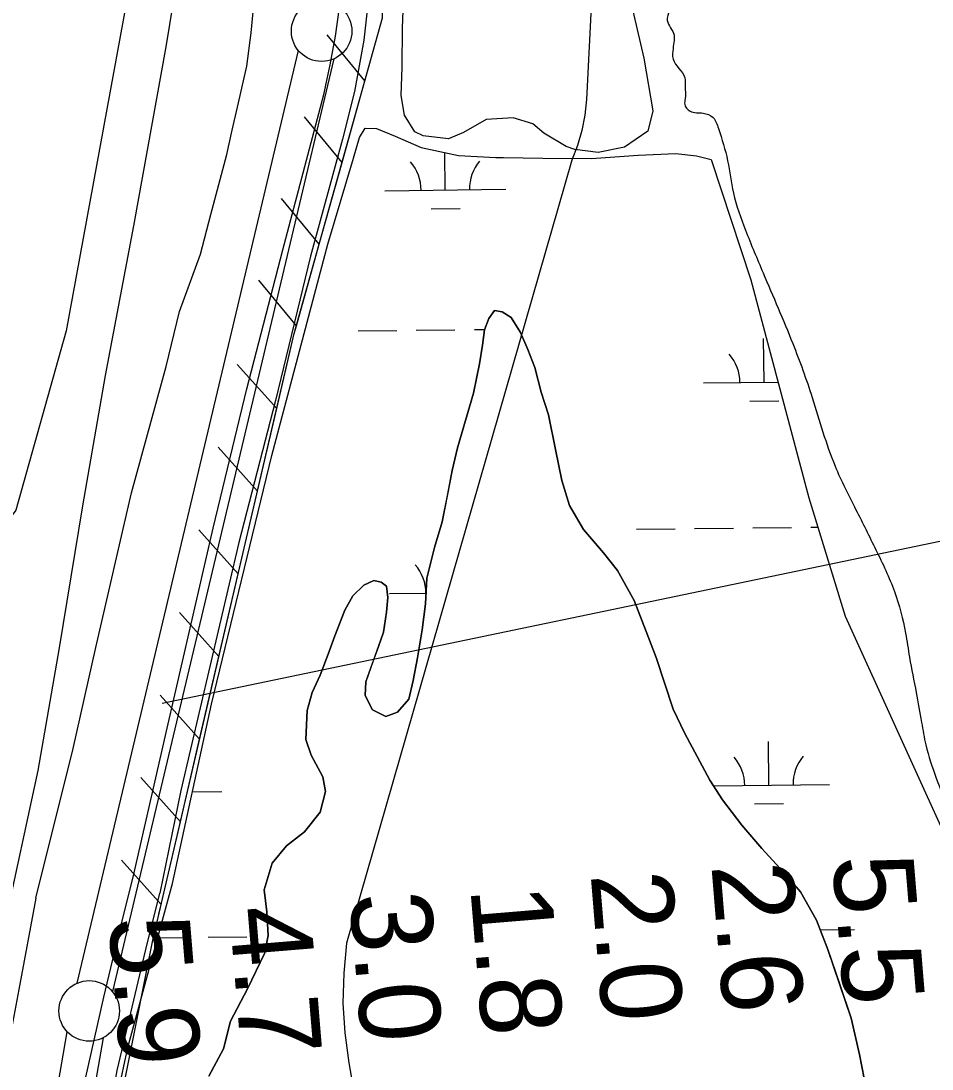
# Model space of a CAD drawing. Extents: x 3694830 to 3732949, y 415201 to 440970.
# Drawn here: x 3715805 to 3716558, y 422528 to 423394 of the extents above; entities that cross this region are included whole.
import ezdxf

# ---------------------------------------------------------------- set-up
doc = ezdxf.new("R2010")
doc.units = 0
for name, color, linetype in [('V-FLOD-BASE', 7, 'Continuous'), ('V-LEVE-TOET', 7, 'Continuous'), ('V-RAIL-TRAK', 7, 'Continuous'), ('V-RIVR-EDGE', 7, 'Continuous'), ('V-RIVR-RANG', 7, 'Continuous'), ('V-RRAP-FSHR', 7, 'Continuous'), ('V-SITE-VEGE', 7, 'Continuous'), ('V-SURV-LINE', 7, 'Continuous'), ('V-TOPO-MINR', 7, 'Continuous'), ('V-TOPO-SHOR', 7, 'Continuous'), ('V-WETL-SWMP', 7, 'Continuous')]:
    doc.layers.add(name, color=color, linetype=linetype)

msp = doc.modelspace()

# ---------------------------------------------------------------- linework, layer by layer
at = {"layer": 'V-FLOD-BASE'}
for points in [[(3716053.01, 423322.64), (3716055.87, 423334.29), (3716058.52, 423345.99), (3716060.97, 423357.73), (3716063.21, 423369.52), (3716065.24, 423381.34), (3716067.06, 423393.2), (3716068.68, 423405.09)], [(3715898.13, 422686.87), (3715926.21, 422809.82), (3715964.19, 422974.98), (3715992.2, 423090), (3716021.8, 423205), (3716053.01, 423322.64)], [(3715861.32, 422013.21), (3715856.48, 422048.35), (3715852.1, 422088.59), (3715850.36, 422117.12), (3715849.12, 422214.47), (3715844.99, 422359.72), (3715844.17, 422401), (3715846.46, 422436.71), (3715848.37, 422453.54), (3715851.79, 422474.47), (3715858.59, 422519.38), (3715873.88, 422587.8), (3715886.74, 422641.92), (3715898.13, 422686.87)]]:
    msp.add_lwpolyline(points, dxfattribs=at)
at = {"layer": 'V-LEVE-TOET'}
for points in [[(3715817.73, 422669.64), (3715848.46, 422793.09), (3715867.2, 422876.47), (3715896.91, 423004.17), (3715925.35, 423108.6), (3715936.34, 423153.98), (3715953.69, 423201.41), (3715962.45, 423234.11), (3715975.59, 423283.7), (3715980, 423303.75), (3715984.4, 423322.75), (3715992.11, 423356.52), (3715995.53, 423383.98), (3716001.38, 423445.27)], [(3716092.74, 423415.43), (3716088.7, 423377.92), (3716080.91, 423335.69), (3716071.03, 423296.12), (3716044.78, 423199.59), (3716015.67, 423080.35), (3715985.53, 422963.24), (3715937.67, 422758.51), (3715920.18, 422673.62)], [(3715817.73, 422669.64), (3715803.59, 422594.17), (3715792.1, 422532.51), (3715786.01, 422485.59), (3715780.9, 422431.33), (3715777.63, 422376.16), (3715777.98, 422329.3), (3715781.11, 422279.69), (3715790.05, 422189.69), (3715797.1, 422106.11), (3715807.99, 422000.49)], [(3715877.82, 422064.43), (3715874.08, 422073.13), (3715867.06, 422091.46), (3715866.07, 422100.19), (3715866.75, 422132.36), (3715866.05, 422164.52), (3715865.85, 422253.2), (3715864.71, 422345.56), (3715865.33, 422386.46), (3715865.55, 422418.63), (3715866.41, 422427.09), (3715867.52, 422435.51), (3715868.87, 422443.9), (3715870.46, 422452.25), (3715872.29, 422460.55), (3715874.37, 422468.79), (3715884.96, 422527.23), (3715908.58, 422627.12), (3715920.18, 422673.62)]]:
    msp.add_lwpolyline(points, dxfattribs=at)
at = {"layer": 'V-RAIL-TRAK'}
msp.add_lwpolyline([(3715982.46, 424206.42), (3715993.76, 424052.97), (3715994.57, 424025.46), (3715995.29, 423987.39), (3715994.86, 423940.86), (3715989.91, 423860.53), (3715973.5, 423684.07), (3715949.84, 423523.54), (3715925.2, 423372.53), (3715898.48, 423224.71), (3715875.15, 423101.19), (3715856.2, 422993.49), (3715837.16, 422876.28), (3715819.32, 422774.92), (3715791.71, 422646.15)], dxfattribs=at)
at = {"layer": 'V-RIVR-EDGE'}
for points in [[(3716285.15, 433216.71), (3716310.38, 433178.21), (3716330.2, 433149.68), (3716351.38, 433122.49), (3716380.66, 433076.75), (3716399.14, 433050.48), (3716447.79, 432976.21), (3716475.25, 432930.47), (3716501.83, 432891.07), (3716527.51, 432851.22), (3716586.04, 432749.34), (3716608.1, 432711.75), (3716608.09, 432707.68), (3716608.07, 432700.45), (3716613.02, 432690.94), (3716627.43, 432664.23), (3716633.27, 432651.55), (3716643.19, 432639.32), (3716675.17, 432589.5), (3716706.24, 432538.33), (3716726.94, 432498.04), (3716741.33, 432463.64), (3716748.51, 432442.82), (3716788.59, 432378.52), (3716817.43, 432339.56), (3716842.2, 432297.45), (3716889.46, 432209.61), (3716920.5, 432144.42), (3716938.04, 432109.56), (3716956.5, 432075.15), (3716988.92, 432022.62), (3717009.18, 431986.85), (3717026.3, 431960.13), (3717062.32, 431897.65), (3717093.37, 431840.15), (3717112.26, 431799.86), (3717149.12, 431711.14), (3717176.54, 431644.61), (3717201.25, 431580.79), (3717210.68, 431556.35), (3717248.47, 431478.94), (3717267.81, 431435.48), (3717289.41, 431392.93), (3717306.48, 431346.77), (3717328.07, 431301.04), (3717339.31, 431276.6), (3717352.34, 431244.01), (3717362.7, 431226.35), (3717376.21, 431205.52), (3717389.26, 431178.36), (3717401.37, 431141.7), (3717407.18, 431113.2), (3717409.87, 431101.89), (3717419.75, 431075.64), (3717452.49, 430968.85), (3717469.09, 430916.81), (3717483.44, 430865.23), (3717505.45, 430810.01), (3717526.57, 430753.44), (3717540.49, 430715.43), (3717579.07, 430593.25), (3717599.25, 430526.28), (3717616.31, 430474.69), (3717628.88, 430437.13), (3717638.74, 430405), (3717647.69, 430364.28), (3717653.48, 430331.72), (3717658.42, 430314.52), (3717667.85, 430290.08), (3717679.53, 430260.66), (3717690.34, 430242.1), (3717695.71, 430221.28), (3717698.37, 430200.03), (3717697.85, 430171.99), (3717701.42, 430152.99), (3717705.91, 430140.77), (3717716.26, 430119.95), (3717727.97, 430100.48), (3717735.6, 430076.49), (3717737.82, 430059.31), (3717749.05, 430029.89), (3717760.76, 430011.77), (3717771.56, 429990.04), (3717776.48, 429968.33), (3717783.19, 429941.63), (3717791.73, 429917.65), (3717803.43, 429898.63), (3717812.42, 429876.45), (3717819.16, 429857.44), (3717834.88, 429816.71), (3717846.52, 429770.11), (3717854.12, 429734.82), (3717863.55, 429706.31), (3717878.83, 429667.39), (3717891.37, 429622.59), (3717903.49, 429586.39), (3717917.82, 429530.29), (3717931.71, 429476.45), (3717959.46, 429363.79), (3717976.51, 429307.23), (3717987.25, 429262.44), (3718014.11, 429153.85), (3718027.51, 429090.07), (3718040.47, 429028.09), (3718052.52, 428962.5), (3718057.84, 428919.98), (3718056.9, 428903.25), (3718056.86, 428887.88), (3718057.71, 428868.43), (3718061.29, 428850.79), (3718065.77, 428833.6), (3718082.36, 428779.3), (3718091.33, 428748.08), (3718100.28, 428710.98), (3718111.45, 428657.14), (3718116.36, 428631.81), (3718128.31, 428525.97), (3718136.77, 428473.05), (3718141.66, 428440.03), (3718152.32, 428360.88), (3718163.9, 428291.22), (3718171.05, 428256.38), (3718178.23, 428236.47), (3718193.92, 428178.55), (3718199.74, 428157.29), (3718197.91, 428150.06), (3718196.52, 428133.33), (3718197.39, 428121.12), (3718204.12, 428098.04), (3718215.36, 428075.41), (3718227.96, 428049.6), (3718240.08, 428011.59), (3718242.71, 427978.58), (3718251.11, 427901.24), (3718254.15, 427852.85), (3718257.69, 427822.1), (3718271.5, 427736.15), (3718281.74, 427671.92), (3718287.91, 427606.34), (3718295.91, 427551.61), (3718303.87, 427477.44), (3718310.12, 427447.13), (3718323.14, 427407.76), (3718345.15, 427350.28), (3718351.41, 427321.78), (3718363.48, 427267.49), (3718378.28, 427217.26), (3718397.99, 427141.25), (3718402.87, 427105.52), (3718405.92, 427056.68), (3718404.86, 426993.38), (3718419.58, 426915.12), (3718427.13, 426857.67), (3718428.77, 426789.85), (3718439.53, 426753.19), (3718453.89, 426709.75), (3718458.33, 426677.18), (3718461.82, 426625.18), (3718465.34, 426583.57), (3718482.71, 426479.53), (3718492.52, 426423.89), (3718501, 426378.2), (3718502.74, 426350.16), (3718512.91, 426256.09), (3718518.23, 426213.12), (3718524.03, 426182.81), (3718533.44, 426148.88), (3718540.93, 426069.28), (3718548.93, 426010.93), (3718557.81, 425944.44), (3718573.42, 425858.94), (3718584.55, 425787.48), (3718587.61, 425745.42), (3718587.56, 425725.97), (3718607.51, 425567.22), (3718614.55, 425488.07), (3718638.22, 425368.64), (3718641.26, 425318.45), (3718641.09, 425249.72), (3718640.1, 425214), (3718649.84, 425130.78), (3718658.73, 425069.26), (3718661.82, 425037.15), (3718660.41, 425016.36), (3718674.96, 424864.4), (3718675.73, 424812.85), (3718692.62, 424694.79), (3718696.05, 424618.82), (3718696.4, 424575.87), (3718706.12, 424484.51), (3718711.87, 424431.59), (3718715.41, 424403.09), (3718735.93, 424289.1), (3718746.6, 424215.37), (3718759.9, 424108.63), (3718772.36, 424027.21), (3718777.72, 423998.26), (3718795.91, 423858.04), (3718805.72, 423804.21), (3718812.44, 423776.61), (3718829, 423707.39), (3718835.67, 423662.61), (3718835.09, 423611.97), (3718835, 423576.7), (3718839.35, 423505.25), (3718842.4, 423460.03), (3718850.42, 423412.53), (3718863.4, 423357.79), (3718870.56, 423326.57), (3718873.56, 423260.55), (3718878.86, 423208.99), (3718893.63, 423148.36), (3718899, 423126.2), (3718912.45, 423080.04), (3718927.23, 423022.58), (3718930.77, 422992.73), (3718937.45, 422950.21), (3718945.92, 422900.45), (3718952.63, 422870.59), (3718968.72, 422795.95), (3718969.56, 422769.72), (3718968.13, 422738.52), (3718972.12, 422707.77), (3718981.05, 422661.17), (3718990.85, 422602.82), (3719006.89, 422506.47), (3719010.81, 422446.32), (3719014.37, 422425.06), (3719022.44, 422393.39), (3719033.2, 422359), (3719050.26, 422307.87), (3719062.77, 422249.05), (3719077.1, 422190.24), (3719087.85, 422149.06)], [(3716330.82, 423439.35), (3716341.85, 423407.99), (3716341.03, 423402.33), (3716339.39, 423394.25), (3716345.02, 423382.1), (3716345.01, 423377.65), (3716344.18, 423371.18), (3716344.16, 423362.29), (3716353.83, 423346.9), (3716354.22, 423340.02), (3716354.19, 423329.51), (3716353.78, 423325.06), (3716358.21, 423319.39), (3716369.12, 423317.75), (3716377.2, 423314.09), (3716381.63, 423305.18), (3716389.24, 423278.47), (3716394.03, 423251.77), (3716404.06, 423221.02), (3716418.53, 423185.8), (3716443.06, 423127.51), (3716459.12, 423082.99), (3716477.99, 423026.33), (3716495.29, 422990.3), (3716511.78, 422957.1), (3716527.06, 422922.69), (3716536.28, 422888.3), (3716539.46, 422868.47), (3716545.05, 422839.35), (3716549.44, 422814.67), (3716553.03, 422796.06), (3716571.9, 422741.42), (3716593.58, 422675.05), (3716607.64, 422637.82), (3716616.87, 422610.7), (3716635.34, 422558.09), (3716647.38, 422520.45), (3716673.89, 422447)]]:
    msp.add_spline(points, degree=3, dxfattribs=at)
at = {"layer": 'V-RIVR-RANG'}
msp.add_line((3715922.14, 422830.69), (3716901.18, 423034.35), dxfattribs=at)
at = {"layer": 'V-RRAP-FSHR'}
for p, q in [((3716089.55, 423344.5), (3716058.52, 423382.27)), ((3716070.71, 423277), (3716039.68, 423314.78)), ((3716051.87, 423209.51), (3716020.84, 423247.28)), ((3716033.03, 423142.01), (3716002, 423179.78)), ((3716016.83, 423073.84), (3715984.21, 423110.25)), ((3716000.89, 423005.6), (3715968.27, 423042.01)), ((3715984.95, 422937.36), (3715952.33, 422973.77)), ((3715969.01, 422869.12), (3715936.39, 422905.53)), ((3715953.07, 422800.88), (3715920.46, 422837.29)), ((3715937.14, 422732.64), (3715904.52, 422769.05)), ((3715921.2, 422664.4), (3715888.58, 422700.81))]:
    msp.add_line(p, q, dxfattribs=at)
for points in [[(3716641.15, 420826.04), (3716497.1, 420943.72), (3716411.63, 421060.5), (3716364.3, 421170.5), (3716321.83, 421303.9), (3716285.1, 421373.79), (3716186.8, 421473.87), (3716066.75, 421590.93), (3715980.47, 421690.03), (3715930.26, 421828.72), (3715913.48, 421896.78), (3715879.02, 422073.91), (3715879.91, 422256.34), (3715873.14, 422428), (3715914.01, 422633.62), (3716031.29, 423135.79), (3716104.08, 423396.54), (3716111.44, 423811.54), (3716102.74, 424148.37), (3716065.57, 424473.12), (3715995.1, 425269.77), (3715894.16, 426351.13), (3715758.55, 427758.05)], [(3716089.55, 423344.5), (3716093.62, 423359.05)], [(3716070.71, 423277), (3716089.55, 423344.5)], [(3716051.87, 423209.51), (3716070.71, 423277)], [(3716033.03, 423142.01), (3716051.87, 423209.51)], [(3716016.83, 423073.84), (3716031.29, 423135.79), (3716033.03, 423142.01)], [(3716000.89, 423005.6), (3716016.83, 423073.84)], [(3715984.95, 422937.36), (3716000.89, 423005.6)], [(3715969.01, 422869.12), (3715984.95, 422937.36)], [(3715953.07, 422800.88), (3715969.01, 422869.12)], [(3715937.14, 422732.64), (3715953.07, 422800.88)], [(3715921.2, 422664.4), (3715937.14, 422732.64)], [(3715919.35, 422656.48), (3715921.2, 422664.4)]]:
    msp.add_lwpolyline(points, dxfattribs=at)
at = {"layer": 'V-SITE-VEGE'}
for points in [[(3715921.04, 423564.26), (3715842.92, 423137.98), (3715801.35, 422989.83), (3715738.71, 422906.86), (3715523.69, 422738.62), (3715255.9, 422552.31), (3714871.15, 422242.78)], [(3716308.92, 423410.38), (3716320.09, 423363.1), (3716327.43, 423319.72), (3716323.41, 423302.73), (3716303.96, 423289.76), (3716282.26, 423285.31), (3716262.94, 423287.81), (3716256, 423290.2), (3716237.54, 423301.19), (3716228.33, 423309.01), (3716212.12, 423313.8), (3716189.68, 423312.46), (3716171.02, 423301.79), (3716158.6, 423296.49), (3716137.73, 423299), (3716130.8, 423302.16), (3716122.42, 423316.16), (3716119.47, 423332.43), (3716120.46, 423355.62), (3716120.75, 423388.11), (3716121.78, 423416.72)]]:
    msp.add_lwpolyline(points, dxfattribs=at)
at = {"layer": 'V-SURV-LINE'}
for points in [[(3715851.88, 422599.33), (3716034.63, 423369.4)], [(3716063.82, 423362.49), (3715881.07, 422592.42)], [(3715824.68, 422448.86), (3715843.69, 422559.29)], [(3715873.25, 422554.2), (3715854.24, 422443.77)]]:
    msp.add_lwpolyline(points, dxfattribs=at)
for centre in [(3716053.84, 423385.39), (3715861.86, 422576.43)]:
    msp.add_circle(centre, 25, dxfattribs=at)
at = {"layer": 'V-TOPO-MINR'}
msp.add_lwpolyline([(3716278.9, 423454.96), (3716272.68, 423328.97), (3716271.29, 423316.02), (3716268.95, 423303.3), (3716265.17, 423290.93), (3716260.44, 423278.8), (3716074.38, 422632.4), (3716072.17, 422607.65), (3716071.48, 422582.93), (3716073.08, 422558.25), (3716076.2, 422533.6), (3716141.8, 422157.11), (3716151.05, 422116.05), (3716162.88, 422075.89), (3716178.58, 422037.07)], dxfattribs=at)
at = {"layer": 'V-TOPO-SHOR'}
for points in [[(3715960.64, 422522.53), (3715972.79, 422545.26), (3715978.57, 422567.93), (3715992.67, 422594.64), (3716006.75, 422623.73), (3716009.81, 422638.84), (3716008.48, 422658.29), (3716006.36, 422676.54), (3716012.95, 422698.43), (3716024.75, 422712.81), (3716039.75, 422724.44), (3716052.74, 422740.42), (3716056.98, 422757.52), (3716054.9, 422769.81), (3716045.24, 422787.61), (3716040.77, 422800.68), (3716041.79, 422824.51), (3716046.05, 422839.24), (3716052.69, 422853.58), (3716059.31, 422871.1), (3716064.76, 422886.23), (3716072.94, 422907.34), (3716079.6, 422919.3), (3716088.67, 422928.1), (3716096.98, 422931.74), (3716102.95, 422930.59), (3716107.34, 422927.05), (3716108.6, 422917.93), (3716107.5, 422905.61), (3716104.84, 422889.31), (3716100.96, 422877.37), (3716096.29, 422864.63), (3716090.45, 422848.3), (3716089.75, 422836.78), (3716095.79, 422824.92), (3716106.95, 422819.44), (3716116.45, 422823.08), (3716125.9, 422833.87), (3716129.36, 422849.39), (3716133.19, 422868.08), (3716136.99, 422891.14), (3716139.61, 422912.6), (3716140.65, 422933.65), (3716147.21, 422959.11), (3716153.41, 422980.2), (3716158, 423003.27), (3716161.82, 423022.75), (3716166.05, 423041.45), (3716179.22, 423086.41), (3716184.2, 423110.67), (3716186.87, 423126.17), (3716188.36, 423138.89), (3716191.87, 423148.05), (3716196.58, 423154.84), (3716202.94, 423153.69), (3716210.52, 423148.98), (3716218.16, 423136.73), (3716224.22, 423122.48), (3716229.89, 423107.83), (3716235.2, 423087.22), (3716241.3, 423068.6), (3716247.07, 423040.06), (3716252.42, 423014.29), (3716258.53, 422993.69), (3716270.19, 422973.92), (3716286.62, 422954.59), (3716298.24, 422939.98), (3716311.92, 422915.46), (3716322.04, 422889.73), (3716330.14, 422868.35), (3716344.35, 422825.57), (3716354.03, 422805.39), (3716364.1, 422786.4), (3716374.57, 422767.02), (3716385.01, 422750.82), (3716401.05, 422729.9), (3716417.47, 422710.56), (3716432.29, 422694.39)], [(3716432.29, 422694.39), (3716449.5, 422674.66), (3716462.78, 422651.34), (3716472.09, 422627.18), (3716481.84, 422598.27), (3716491.18, 422570.54), (3716498.15, 422540.42), (3716503.93, 422510.68)]]:
    msp.add_lwpolyline(points, dxfattribs=at)
at = {"layer": 'V-WETL-SWMP'}
for p, q in [((3716085.07, 423297.52), (3716089.78, 423305.21)), ((3716089.78, 423305.21), (3716099.06, 423305.13)), ((3716099.06, 423305.13), (3716114.48, 423298.8)), ((3716080.28, 423280.54), (3716085.07, 423297.52)), ((3716114.48, 423298.8), (3716136.05, 423289.32)), ((3716136.05, 423289.32), (3716166.94, 423282.85)), ((3716156.05, 423254.27), (3716155.68, 423285.21)), ((3716315.46, 423283.05), (3716346.41, 423284.32)), ((3716346.41, 423284.32), (3716363.42, 423282.61)), ((3716059.11, 423209.5), (3716080.28, 423280.54)), ((3716166.94, 423282.85), (3716197.86, 423281.02)), ((3716197.86, 423281.02), (3716204.05, 423280.97)), ((3716204.05, 423280.97), (3716236.54, 423280.67)), ((3716236.54, 423280.67), (3716276.76, 423280.31)), ((3716276.76, 423280.31), (3716315.46, 423283.05)), ((3716363.42, 423282.61), (3716375.76, 423279.41)), ((3716375.76, 423279.41), (3716408.47, 423180.04)), ((3716106.05, 423253.67), (3716206.05, 423254.87)), ((3716144.23, 423238.7), (3716168.23, 423238.98)), ((3716031.89, 423107.65), (3716059.11, 423209.5)), ((3716408.47, 423180.04), (3716456.35, 423000.15)), ((3716196.58, 423154.84), (3716191.87, 423148.05)), ((3716202.94, 423153.69), (3716196.58, 423154.84)), ((3716191.87, 423148.05), (3716188.36, 423138.89)), ((3716210.52, 423148.98), (3716202.94, 423153.69)), ((3716218.16, 423136.73), (3716210.52, 423148.98)), ((3716084.02, 423137.97), (3716116.02, 423138.35)), ((3716132.02, 423138.54), (3716164.02, 423138.92)), ((3716180.02, 423139.12), (3716188.49, 423139.22)), ((3716188.36, 423138.89), (3716186.87, 423126.18)), ((3716224.22, 423122.48), (3716218.16, 423136.73)), ((3716419.4, 423095.54), (3716418.97, 423131.53)), ((3716186.87, 423126.18), (3716184.2, 423110.67)), ((3716229.89, 423107.83), (3716224.22, 423122.48)), ((3716184.2, 423110.67), (3716179.22, 423086.41)), ((3716012.67, 423035.11), (3716031.89, 423107.65)), ((3716235.2, 423087.22), (3716229.89, 423107.83)), ((3716369.4, 423094.94), (3716430.92, 423095.68)), ((3716179.22, 423086.41), (3716166.06, 423041.44)), ((3716241.3, 423068.61), (3716235.2, 423087.22)), ((3716407.58, 423079.96), (3716431.58, 423080.25)), ((3716247.07, 423040.06), (3716241.3, 423068.61)), ((3716166.06, 423041.44), (3716161.83, 423022.75)), ((3715962.85, 422829.81), (3716012.67, 423035.11)), ((3716252.42, 423014.29), (3716247.07, 423040.06)), ((3716161.83, 423022.75), (3716153.41, 422980.2)), ((3716258.53, 422993.69), (3716252.42, 423014.29)), ((3716456.35, 423000.15), (3716486.4, 422902.41)), ((3716270.19, 422973.92), (3716258.53, 422993.69)), ((3716153.41, 422980.2), (3716147.21, 422959.11)), ((3716286.61, 422954.59), (3716270.19, 422973.92)), ((3716313.99, 422974.2), (3716345.99, 422974.58)), ((3716361.99, 422974.77), (3716393.99, 422975.16)), ((3716409.99, 422975.35), (3716441.98, 422975.73)), ((3716457.98, 422975.92), (3716463.78, 422975.99)), ((3716147.21, 422959.11), (3716140.65, 422933.65)), ((3716298.24, 422939.98), (3716286.61, 422954.59)), ((3716311.92, 422915.46), (3716298.24, 422939.98)), ((3716096.98, 422931.74), (3716088.67, 422928.1)), ((3716102.95, 422930.59), (3716096.98, 422931.74)), ((3716107.34, 422927.05), (3716102.95, 422930.59)), ((3716140.65, 422933.65), (3716139.61, 422912.6)), ((3716088.67, 422928.1), (3716079.61, 422919.3)), ((3716108.6, 422917.93), (3716107.34, 422927.05)), ((3716110.02, 422921.02), (3716140.04, 422921.38)), ((3716079.61, 422919.3), (3716072.94, 422907.34)), ((3716107.5, 422905.61), (3716108.6, 422917.93)), ((3716139.61, 422912.6), (3716136.99, 422891.14)), ((3716322.04, 422889.73), (3716311.92, 422915.46)), ((3716072.94, 422907.34), (3716064.76, 422886.23)), ((3716104.84, 422889.31), (3716107.5, 422905.61)), ((3716486.4, 422902.41), (3716593.03, 422667.55)), ((3716064.76, 422886.23), (3716059.32, 422871.1)), ((3716100.96, 422877.37), (3716104.84, 422889.31)), ((3716136.99, 422891.14), (3716133.19, 422868.08)), ((3716330.14, 422868.35), (3716322.04, 422889.73)), ((3716090.46, 422848.3), (3716100.96, 422877.37)), ((3716059.32, 422871.1), (3716052.7, 422853.58)), ((3716344.35, 422825.57), (3716330.14, 422868.35)), ((3716133.19, 422868.08), (3716129.36, 422849.39)), ((3716052.7, 422853.58), (3716046.05, 422839.24)), ((3716089.75, 422836.78), (3716090.46, 422848.3)), ((3716129.36, 422849.39), (3716125.9, 422833.88)), ((3716046.05, 422839.24), (3716041.79, 422824.52)), ((3716095.79, 422824.92), (3716089.75, 422836.78)), ((3716125.9, 422833.88), (3716116.45, 422823.08)), ((3715930.56, 422681.58), (3715962.85, 422829.81)), ((3716106.95, 422819.44), (3716095.79, 422824.92)), ((3716354.03, 422805.39), (3716344.35, 422825.57)), ((3716041.79, 422824.52), (3716040.78, 422800.68)), ((3716116.45, 422823.08), (3716106.95, 422819.44)), ((3716040.78, 422800.68), (3716045.24, 422787.61)), ((3716364.1, 422786.4), (3716354.03, 422805.39)), ((3716423.37, 422762.89), (3716422.94, 422798.88)), ((3716045.24, 422787.61), (3716054.91, 422769.82)), ((3716374.57, 422767.02), (3716364.1, 422786.4)), ((3716054.91, 422769.82), (3716056.98, 422757.52)), ((3716385.01, 422750.82), (3716374.57, 422767.02)), ((3715947.04, 422757.21), (3715971.49, 422757.5)), ((3716056.98, 422757.52), (3716052.74, 422740.42)), ((3716377.59, 422762.34), (3716473.36, 422763.48)), ((3716401.05, 422729.9), (3716385.01, 422750.82)), ((3716411.55, 422747.31), (3716435.55, 422747.6)), ((3716052.74, 422740.42), (3716039.76, 422724.44)), ((3716417.47, 422710.56), (3716401.05, 422729.9)), ((3716039.76, 422724.44), (3716024.75, 422712.81)), ((3716024.75, 422712.81), (3716012.95, 422698.43)), ((3716432.29, 422694.39), (3716417.47, 422710.56)), ((3716012.95, 422698.43), (3716006.36, 422676.54)), ((3716449.51, 422674.66), (3716432.29, 422694.39)), ((3715893.89, 422546.21), (3715930.56, 422681.58)), ((3716006.36, 422676.54), (3716008.48, 422658.29)), ((3716462.78, 422651.34), (3716449.51, 422674.66)), ((3716008.48, 422658.29), (3716009.82, 422638.85)), ((3716472.09, 422627.18), (3716462.78, 422651.34)), ((3716465.87, 422643.31), (3716493.95, 422643.65)), ((3715918.43, 422636.78), (3715944.08, 422637.09)), ((3715960.08, 422637.28), (3715992.08, 422637.66)), ((3716009.82, 422638.85), (3716006.75, 422623.73)), ((3716491.18, 422570.54), (3716472.09, 422627.18)), ((3716006.75, 422623.73), (3715992.67, 422594.64)), ((3715992.67, 422594.64), (3715978.58, 422567.93)), ((3715978.58, 422567.93), (3715972.79, 422545.26)), ((3716498.15, 422540.42), (3716491.18, 422570.54)), ((3715879.68, 422479.93), (3715893.89, 422546.21)), ((3715972.79, 422545.26), (3715960.65, 422522.54)), ((3716503.93, 422510.68), (3716498.15, 422540.42))]:
    msp.add_line(p, q, dxfattribs=at)
for centre, start, end in [((3716100.81, 423254.09), 359.91153, 41.45518), ((3716211.28, 423255.4), 139.91153, 181.45519), ((3716364.15, 423095.35), 359.91153, 41.45518), ((3716104.77, 422921.43), 359.91153, 41.45518), ((3716368.12, 422762.7), 359.91153, 41.45518), ((3716478.6, 422764.02), 139.91153, 181.45519)]:
    msp.add_arc(centre, 35.25, start, end, dxfattribs=at)

# ---------------------------------------------------------------- texts
at = {"layer": 'V-RIVR-RANG'}
for s, p in [('2.6', (3716375.8, 422696.76)), ('5.5', (3716475.59, 422703.39)), ('2.0', (3716276.07, 422689.34)), ('3.0', (3716076.79, 422672.4)), ('1.8', (3716176.67, 422677.98)), ('4.7', (3715977.39, 422661.04)), ('5.9', (3715877.72, 422652.83))]:
    msp.add_text(s, height=67, rotation=274.71833, dxfattribs=at).set_placement(p)

doc.saveas('drawing.dxf')
